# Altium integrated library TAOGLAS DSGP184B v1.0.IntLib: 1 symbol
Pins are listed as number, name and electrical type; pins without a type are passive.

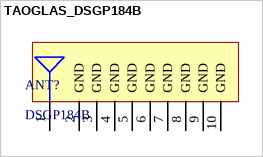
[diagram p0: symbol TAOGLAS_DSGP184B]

## TAOGLAS_DSGP184B
designator ANT?, comment DSGP184B
GPS L1 / GALILEO E1 1575.42MHz 18*18*4mm Ceramic Patch SMD Antenna; ComponentLibStatus: Created; MFG: Taoglas; Temp_High: +85C; Temp_Low: -40C
footprint TAOGLAS_DSGP184B (GPS L1 / GALILEO E1 1575.42MHz 18*18*4mm Ceramic Patch SMD Antenna)
pins: 1 RF FEED, 2 GND, 3 GND, 4 GND, 5 GND, 6 GND, 7 GND, 8 GND, 9 GND, 10 GND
